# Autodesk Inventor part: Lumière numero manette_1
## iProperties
Created: 2010-07
Part Number: Lumière numero manette_1
Document SubType Name: Modeling
Designer: eric
Density: 1 g/cm^3
Author: eric
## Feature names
1. Base1
